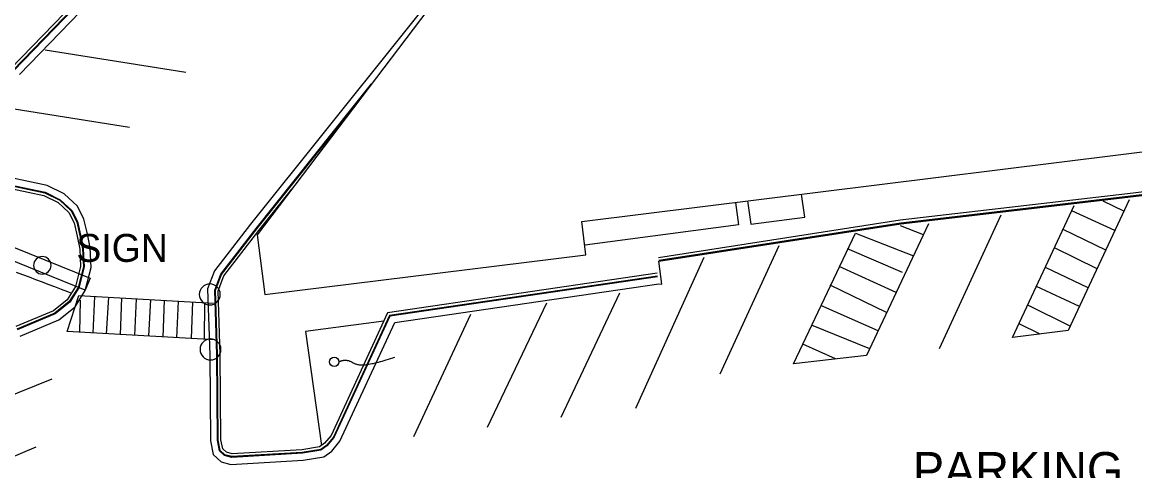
# Model space of a CAD drawing. Extents: x 1901471 to 1963503, y 756461 to 799997.
# Drawn here: x 1929649.4 to 1929808.6, y 772512.1 to 772576.3 of the extents above; entities that cross this region are included whole.
import ezdxf

# ---------------------------------------------------------------- set-up
doc = ezdxf.new("R2010")
doc.units = 0
for name, color, linetype in [('Default', 7, 'Continuous'), ('RD_EX_Bldg', 7, 'Continuous'), ('RD_EX_BldgApp', 7, 'Continuous'), ('RD_EX_Conc', 7, 'Continuous'), ('RD_EX_Misc', 7, 'Continuous'), ('RD_EX_Road', 7, 'Continuous'), ('RD_EX_SU_Telecom', 7, 'Continuous')]:
    doc.layers.add(name, color=color, linetype=linetype)

# ---------------------------------------------------------------- blocks, each defined once
blk = doc.blocks.new('POST')
at = {"layer": 'Default'}
for start, end in [(90, 270), (270, 90)]:
    blk.add_arc((0, 0), 0.127, start, end, dxfattribs=at)
blk = doc.blocks.new('SIGNPOST')
at = {"layer": 'Default'}
for start, end in [(90, 270), (270, 90)]:
    blk.add_arc((0, 0), 0.127, start, end, dxfattribs=at)

msp = doc.modelspace()

# ---------------------------------------------------------------- linework, layer by layer
at = {"layer": 'RD_EX_Bldg'}
for points in [[(1929729.45, 772547.77), (1929839.97, 772561.48), (1929835.82, 772594.93), (1929825.31, 772593.62), (1929824.38, 772601.12), (1929804.33, 772598.63), (1929804, 772601.24), (1929742.69, 772593.63), (1929743.42, 772587.74), (1929711.76, 772583.81), (1929683.02, 772545.83), (1929684.08, 772537.3), (1929730.04, 772543.01)], [(1929646.09, 772544.89), (1929659.08, 772539.64), (1929658.38, 772537.91), (1929645.39, 772543.16)]]:
    msp.add_lwpolyline(points, close=True, dxfattribs=at)
at = {"layer": 'RD_EX_BldgApp'}
for points in [[(1929753.62, 772547.36), (1929761.34, 772548.4), (1929760.9, 772551.67)], [(1929751.45, 772550.49), (1929751.87, 772547.27)], [(1929753.17, 772550.71), (1929753.62, 772547.36)], [(1929751.87, 772547.27), (1929729.87, 772544.38)]]:
    msp.add_lwpolyline(points, dxfattribs=at)
at = {"layer": 'RD_EX_Conc'}
for points in [[(1929818.65, 772665.59), (1929787.63, 772654.66), (1929748.03, 772640.8), (1929705.53, 772625.99), (1929700.95, 772619.84), (1929709.34, 772614.36), (1929711.28, 772612.96), (1929711.56, 772612.25), (1929711.57, 772611.67), (1929711.15, 772611.01), (1929710.56, 772610.45), (1929709.71, 772610.24), (1929708.74, 772610.02), (1929689.83, 772613.26), (1929674.02, 772596.83), (1929647.69, 772569.61)], [(1929818.56, 772665.14), (1929787.76, 772654.28), (1929748.16, 772640.43), (1929705.78, 772625.66), (1929701.53, 772619.94), (1929709.57, 772614.69), (1929711.61, 772613.22), (1929711.96, 772612.32), (1929711.97, 772611.56), (1929711.46, 772610.75), (1929710.77, 772610.09), (1929709.81, 772609.85), (1929708.75, 772609.61), (1929689.97, 772612.83), (1929674.31, 772596.55), (1929648.04, 772569.39)], [(1929818.54, 772665.03), (1929787.79, 772654.19), (1929748.2, 772640.33), (1929705.84, 772625.57), (1929701.67, 772619.96), (1929709.62, 772614.77), (1929711.7, 772613.28), (1929712.06, 772612.34), (1929712.07, 772611.53), (1929711.54, 772610.69), (1929710.82, 772610), (1929709.83, 772609.75), (1929708.75, 772609.51), (1929690.01, 772612.73), (1929674.38, 772596.48), (1929648.13, 772569.34)], [(1929740.3, 772539.85), (1929702, 772534.22), (1929693.99, 772516.85), (1929692.98, 772515.64), (1929692.13, 772515.04), (1929689.46, 772514.58), (1929679.35, 772514), (1929678.33, 772514.28), (1929677.62, 772514.95), (1929677.3, 772516.45), (1929677.21, 772528.65), (1929676.92, 772537.93), (1929677.78, 772540.21), (1929682.85, 772546.76), (1929699.38, 772567.45)], [(1929740.29, 772539.94), (1929701.93, 772534.31), (1929693.91, 772516.91), (1929692.91, 772515.71), (1929692.09, 772515.13), (1929689.45, 772514.68), (1929679.36, 772514.1), (1929678.38, 772514.37), (1929677.71, 772515), (1929677.4, 772516.46), (1929677.31, 772528.66), (1929677.02, 772537.92), (1929677.87, 772540.17), (1929682.93, 772546.7), (1929697.1, 772564.44)], [(1929838.73, 772555.48), (1929807.51, 772551.73), (1929775.02, 772547.93), (1929740.4, 772542.57)], [(1929838.78, 772555.08), (1929807.56, 772551.33), (1929775.08, 772547.53), (1929740.46, 772542.18)], [(1929643.47, 772553.37), (1929652.48, 772551.48), (1929654.54, 772550.46), (1929656.06, 772549.04), (1929656.79, 772547.59), (1929657.24, 772545.67), (1929657.62, 772543.8), (1929657.73, 772541.33), (1929657, 772538.47), (1929655.81, 772536.57), (1929653.83, 772534.99), (1929648.47, 772532.71)], [(1929643.84, 772553.7), (1929652.61, 772551.86), (1929654.77, 772550.79), (1929656.38, 772549.29), (1929657.17, 772547.73), (1929657.63, 772545.76), (1929658.02, 772543.84), (1929658.02, 772543.84), (1929658.13, 772541.29), (1929657.37, 772538.31), (1929656.11, 772536.3), (1929654.04, 772534.64), (1929648.63, 772532.34)], [(1929643.93, 772553.78), (1929652.64, 772551.96), (1929654.83, 772550.88), (1929656.46, 772549.35), (1929657.27, 772547.77), (1929657.73, 772545.78), (1929658.12, 772543.86), (1929658.12, 772543.86), (1929658.23, 772541.28), (1929657.47, 772538.27), (1929656.19, 772536.23), (1929654.09, 772534.55), (1929648.67, 772532.25)], [(1929740.23, 772540.34), (1929701.65, 772534.67), (1929693.57, 772517.12), (1929692.63, 772516.01), (1929691.93, 772515.51), (1929689.41, 772515.08), (1929679.4, 772514.5), (1929678.59, 772514.73), (1929678.08, 772515.21), (1929677.8, 772516.5), (1929677.71, 772528.66), (1929677.42, 772537.85), (1929678.22, 772539.97), (1929683.24, 772546.45), (1929687.98, 772552.38)], [(1929648.49, 772540.53), (1929649.43, 772540.18), (1929650.36, 772539.82), (1929651.3, 772539.47), (1929652.23, 772539.11), (1929653.06, 772538.8), (1929653.99, 772538.44), (1929654.93, 772538.09), (1929655.86, 772537.73), (1929656.41, 772537.52)], [(1929701.1, 772533.48), (1929689.93, 772532.03), (1929692.18, 772515.69)]]:
    msp.add_lwpolyline(points, dxfattribs=at)
at = {"layer": 'RD_EX_Road'}
for points in [[(1929649, 772568.8), (1929675.1, 772595.79), (1929690.36, 772611.65), (1929708.78, 772608.49), (1929710.06, 772608.78), (1929711.32, 772609.1), (1929712.32, 772610.05), (1929713.07, 772611.24), (1929713.06, 772612.53), (1929712.52, 772613.92), (1929710.19, 772615.6), (1929703.11, 772620.22), (1929706.46, 772624.73), (1929748.53, 772639.39), (1929788.12, 772653.24), (1929818.34, 772663.9)], [(1929714.42, 772587.89), (1929682.06, 772547.38), (1929676.9, 772540.71), (1929675.91, 772538.1), (1929676.21, 772528.64), (1929676.3, 772516.34), (1929676.71, 772514.43), (1929677.83, 772513.38), (1929679.24, 772512.99), (1929689.58, 772513.58), (1929692.52, 772514.09), (1929693.66, 772514.9), (1929694.84, 772516.31), (1929702.68, 772533.31), (1929740.45, 772538.86), (1929740.9, 772538.81), (1929740.47, 772542.08), (1929775.09, 772547.44), (1929807.57, 772551.23), (1929838.79, 772554.98)], [(1929672.8, 772569.11), (1929652.65, 772572.29)], [(1929664.74, 772561.22), (1929648.23, 772563.83)], [(1929649.08, 772531.33), (1929654.61, 772533.69), (1929656.95, 772535.56), (1929658.4, 772537.87), (1929659.23, 772541.18), (1929659.12, 772543.98), (1929659.12, 772543.98), (1929658.71, 772545.99), (1929658.21, 772548.11), (1929657.28, 772549.96), (1929655.4, 772551.71), (1929652.97, 772552.91), (1929644.86, 772554.61)], [(1929807.78, 772550.87), (1929799.06, 772532.14), (1929791.09, 772531.14), (1929799.92, 772550.05)], [(1929807.03, 772549.26), (1929804.05, 772550.65)], [(1929789.41, 772548.67), (1929780.59, 772529.52)], [(1929805.73, 772546.46), (1929799.57, 772549.31)], [(1929779.06, 772547.42), (1929770.19, 772528.58), (1929759.73, 772527.39), (1929768.61, 772546.11), (1929776.9, 772542.83)], [(1929778.32, 772545.85), (1929775.06, 772547.12)], [(1929804.43, 772543.67), (1929798.31, 772546.6)], [(1929757.62, 772544.29), (1929749.2, 772525.91)], [(1929775.34, 772540.44), (1929767.45, 772543.85)], [(1929803.18, 772541), (1929797.09, 772544)], [(1929746.92, 772542.6), (1929737.13, 772520.97)], [(1929774.43, 772537.59), (1929766.27, 772541.33)], [(1929801.91, 772538.28), (1929795.78, 772541.19)], [(1929773.07, 772534.71), (1929765.01, 772538.64)], [(1929800.66, 772535.58), (1929794.5, 772538.44)], [(1929676.96, 772530.8), (1929655.83, 772531.99), (1929657.46, 772537.17), (1929676.76, 772536.09)], [(1929659.51, 772531.79), (1929659.77, 772537.04)], [(1929661.45, 772531.68), (1929661.77, 772536.93)], [(1929663.42, 772531.56), (1929663.61, 772536.83)], [(1929734.85, 772537.49), (1929726.44, 772519.72)], [(1929657.61, 772531.89), (1929657.73, 772536.48)], [(1929665.5, 772531.45), (1929665.74, 772536.71)], [(1929667.48, 772531.33), (1929667.77, 772536.59)], [(1929669.56, 772531.22), (1929669.74, 772536.48)], [(1929671.5, 772531.11), (1929671.73, 772536.37)], [(1929673.58, 772530.99), (1929673.81, 772536.26)], [(1929675.48, 772530.88), (1929675.49, 772536.16)], [(1929724.41, 772536.08), (1929715.89, 772518.26)], [(1929771.84, 772532.09), (1929763.65, 772535.73)], [(1929799.35, 772532.77), (1929793.26, 772535.78)], [(1929713.54, 772534.44), (1929705.38, 772516.95)], [(1929770.64, 772529.55), (1929762.33, 772532.93)], [(1929795.04, 772531.64), (1929792.02, 772533.12)], [(1929765.73, 772528.08), (1929761.06, 772530.22)], [(1929653.6, 772525.18), (1929634.9, 772517.64)], [(1929651.32, 772515.46), (1929632.21, 772507.35)]]:
    msp.add_lwpolyline(points, dxfattribs=at)
at = {"layer": 'RD_EX_SU_Telecom'}
msp.add_circle((1929694.02, 772527.67), 0.66, dxfattribs=at)
msp.add_open_spline([(1929694.68, 772527.67), (1929695.68, 772528.22), (1929698.03, 772526.74), (1929702.71, 772528.34)], degree=2, dxfattribs=at)

# ---------------------------------------------------------------- block references
at = {"layer": 'RD_EX_Bldg', "xscale": 9.84251968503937, "yscale": 9.84251968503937}
msp.add_blockref('SIGNPOST', (1929652.26, 772541.48), dxfattribs=at)
at = {"layer": 'RD_EX_Misc', "xscale": 11.811023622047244, "yscale": 11.811023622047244}
for p in [(1929676.22, 772537.32), (1929676.32, 772529.45)]:
    msp.add_blockref('POST', p, dxfattribs=at)

# ---------------------------------------------------------------- texts
at = {"layer": 'RD_EX_Road'}
for s, height, p in [('SIGN', 4, (1929657.13, 772541.98)), ('PARKING', 5, (1929776.83, 772509.76))]:
    msp.add_text(s, height=height, dxfattribs=at).set_placement(p)

doc.saveas('drawing.dxf')
